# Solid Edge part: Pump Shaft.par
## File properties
Title: Pump Shaft
Author: Dan
Comments: Rely Investment Cast Shrinkage  2.6%:  X 1.026 Measured Sizes.  EN 19   Die No 3669  Machine  Heat treat to Condition T  Grind  Nitride, Silver Grey Finish
Template: Normal Colour.par
Last saved by: Dan
Revision: 112
Application: Solid Edge
Density: 7.85 kg/dm^3
Accuracy: 0.99
Document Number: P52-003
Project Name: Piston Pump P52
Material: steel en19
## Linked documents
SPLINE1 005UZCMR.par
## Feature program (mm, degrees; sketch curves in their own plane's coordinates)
sketch for "unnamed Protrusion 1" plane through (0, 0, 0) normal (0, 0, 1) x-axis (1, 0, 0)
extrude "unnamed Protrusion 1" add finite 92 along +normal
boolean "unnamed Boolean 1"
sketch for "ExtrudedCutout_1" plane through (0, 0, 0) normal (0, 0, -1) x-axis (0, 1, 0)
  line (15.7162, 3) -> (17.2409, 3)
  arc centre (0, 0) radius 17.5 from (17.2409, -3) to (17.2409, 3) ccw
  line (17.2409, -3) -> (15.7162, -3)
  arc centre (15.7162, -3.8) radius 0.8 from (15.7162, -3) to (15.3507, -4.5116) ccw
  arc centre (0, 0) radius 16 from (15.3507, -4.5116) to (14.0448, -7.6644) cw
  arc centre (13.8001, -8.426) radius 0.8 from (13.2344, -8.9917) to (14.0448, -7.6644) cw
  line (13.2344, -8.9917) -> (14.3125, -10.0699)
  arc centre (0, 0) radius 17.5 from (10.0699, -14.3125) to (14.3125, -10.0699) ccw
  line (10.0699, -14.3125) -> (8.9917, -13.2344)
  arc centre (8.426, -13.8001) radius 0.8 from (8.9917, -13.2344) to (7.6644, -14.0448) ccw
  arc centre (0, 0) radius 16 from (7.6644, -14.0448) to (4.5116, -15.3507) cw
  arc centre (3.8, -15.7162) radius 0.8 from (3, -15.7162) to (4.5116, -15.3507) cw
  line (3, -15.7162) -> (3, -17.2409)
  arc centre (0, 0) radius 17.5 from (-3, -17.2409) to (3, -17.2409) ccw
  line (-3, -17.2409) -> (-3, -15.7162)
  arc centre (-3.8, -15.7162) radius 0.8 from (-3, -15.7162) to (-4.5116, -15.3507) ccw
  arc centre (0, 0) radius 16 from (-4.5116, -15.3507) to (-7.6644, -14.0448) cw
  arc centre (-8.426, -13.8001) radius 0.8 from (-8.9917, -13.2344) to (-7.6644, -14.0448) cw
  line (-8.9917, -13.2344) -> (-10.0699, -14.3125)
  arc centre (0, 0) radius 17.5 from (-14.3125, -10.0699) to (-10.0699, -14.3125) ccw
  line (-14.3125, -10.0699) -> (-13.2344, -8.9917)
  arc centre (-13.8001, -8.426) radius 0.8 from (-13.2344, -8.9917) to (-14.0448, -7.6644) ccw
  arc centre (0, 0) radius 16 from (-14.0448, -7.6644) to (-15.3507, -4.5116) cw
  arc centre (-15.7162, -3.8) radius 0.8 from (-15.7162, -3) to (-15.3507, -4.5116) cw
  line (-15.7162, -3) -> (-17.2409, -3)
  arc centre (0, 0) radius 17.5 from (-17.2409, 3) to (-17.2409, -3) ccw
  line (-17.2409, 3) -> (-15.7162, 3)
  arc centre (-15.7162, 3.8) radius 0.8 from (-15.7162, 3) to (-15.3507, 4.5116) ccw
  arc centre (0, 0) radius 16 from (-15.3507, 4.5116) to (-14.0448, 7.6644) cw
  arc centre (-13.8001, 8.426) radius 0.8 from (-13.2344, 8.9917) to (-14.0448, 7.6644) cw
  line (-13.2344, 8.9917) -> (-14.3125, 10.0699)
  arc centre (0, 0) radius 17.5 from (-10.0699, 14.3125) to (-14.3125, 10.0699) ccw
  line (-10.0699, 14.3125) -> (-8.9917, 13.2344)
  arc centre (-8.426, 13.8001) radius 0.8 from (-8.9917, 13.2344) to (-7.6644, 14.0448) ccw
  arc centre (0, 0) radius 16 from (-7.6644, 14.0448) to (-4.5116, 15.3507) cw
  arc centre (-3.8, 15.7162) radius 0.8 from (-3, 15.7162) to (-4.5116, 15.3507) cw
  line (-3, 15.7162) -> (-3, 17.2409)
  arc centre (0, 0) radius 17.5 from (3, 17.2409) to (-3, 17.2409) ccw
  line (3, 17.2409) -> (3, 15.7162)
  arc centre (3.8, 15.7162) radius 0.8 from (3, 15.7162) to (4.5116, 15.3507) ccw
  arc centre (0, 0) radius 16 from (4.5116, 15.3507) to (7.6644, 14.0448) cw
  arc centre (8.426, 13.8001) radius 0.8 from (8.9917, 13.2344) to (7.6644, 14.0448) cw
  line (8.9917, 13.2344) -> (10.0699, 14.3125)
  arc centre (0, 0) radius 17.5 from (14.3125, 10.0699) to (10.0699, 14.3125) ccw
  line (14.3125, 10.0699) -> (13.2344, 8.9917)
  arc centre (13.8001, 8.426) radius 0.8 from (13.2344, 8.9917) to (14.0448, 7.6644) ccw
  arc centre (0, 0) radius 16 from (14.0448, 7.6644) to (15.3507, 4.5116) cw
  arc centre (15.7162, 3.8) radius 0.8 from (15.7162, 3) to (15.3507, 4.5116) cw
extrude "ExtrudedCutout_1" cut finite 40 along -normal
sketch for "unnamed Cutout 1" plane through (0, 0, 0) normal (0, 0, 1) x-axis (1, 0, 0)
extrude "unnamed Cutout 1" cut to key point along +normal
pattern "unnamed Pattern 1" of "unnamed Cutout 1"
extrude "unnamed Cutout 2" cut finite 40
extrude "unnamed Cutout 3" cut finite 40
extrude "unnamed Cutout 4" cut finite 40
extrude "unnamed Cutout 5" cut finite 40
extrude "unnamed Cutout 6" cut finite 40
extrude "unnamed Cutout 7" cut finite 40
extrude "unnamed Cutout 8" cut finite 40
sketch for "ExtrudedCutout_12" plane through (0, 0, 0) normal (0, 0, -1) x-axis (-1, 0, 0)
extrude "ExtrudedCutout_12" cut finite 40 along -normal
sketch for "unnamed RevolvedCutout 1" plane through (0, 0, 0) normal (0, -1, 0) x-axis (1, 0, 0)
  line (17.5, 40) -> (15, 40)
  line (15, 40) -> (15, 43)
  line (15, 43) -> (17.5, 43)
revolve "unnamed RevolvedCutout 1" cut full turn 360 deg
sketch for "unnamed RevolvedProtrusion 1" plane through (0, 0, 0) normal (1, 0, 0) x-axis (0, 1, 0)
  line (0, 92) -> (20, 92)
  line (20, 92) -> (20, 94)
  line (20, 94) -> (22, 94)
  line (22, 94) -> (22, 106)
  line (22, 106) -> (45, 106)
  line (45, 106) -> (45, 140)
  line (45, 140) -> (15.5086, 156.897)
  arc centre (17, 159.5) radius 3 from (14, 159.5) to (15.5086, 156.897) ccw
  line (14, 159.5) -> (14, 189.5)
  line (14, 189.5) -> (0, 189.5)
revolve "unnamed RevolvedProtrusion 1" add full turn 360 deg about sketch line (0, 189.5) -> (0, 92)
sketch for "unnamed RevolvedCutout 2" plane through (0, 0, 0) normal (1, 0, 0) x-axis (0, 1, 0)
  line (-44.2691, 105.6092) -> (-14.1455, 114.8189)
  line (-14.1455, 114.8189) -> (-25.8403, 153.0711)
  line (-25.8403, 153.0711) -> (-40.9152, 153.0711)
revolve "unnamed RevolvedCutout 2" cut full turn 360 deg about sketch line (2.0265, 137.1696) -> (-6.8733, 166.2795)
sketch for "Cutout_2" plane through (0, -0.5172, 106) normal (0, 0, -1) x-axis (-1, 0, 0)
  hole centre (0, 32.8172) bore radius 5
hole "Cutout_2" diameter 10 finite
sketch for "unnamed RevolvedCutout 3" plane through (0, 0, 0) normal (1, 0, 0) x-axis (0, 1, 0)
  line (41.5, 106) -> (41.5, 122.5158)
  arc centre (44.5, 122.5158) radius 3 from (44.5, 125.5158) to (41.5, 122.5158) ccw
  line (44.5, 125.5158) -> (49.5655, 125.5158)
  line (49.5655, 125.5158) -> (49.5655, 106)
  line (49.5655, 106) -> (41.5, 106)
revolve "unnamed RevolvedCutout 3" cut full turn 360 deg about sketch line (1.0045, 119.4508) -> (3.9475, 109.8248)
sketch for "unnamed RevolvedCutout 4" plane through (0, 0, 0) normal (1, 0, 0) x-axis (0, 1, 0)
revolve "unnamed RevolvedCutout 4" cut full turn 360 deg about sketch line (6.1623, 123.6419) -> (-1.2967, 148.0393)
sketch for "unnamed Cutout 9" plane through (0, 0, 0) normal (1, 0, 0) x-axis (0, 1, 0)
extrude "unnamed Cutout 9" cut through
lofted protrusion "unnamed LoftedProtrusion 1"
sketch for "Hole_9" plane through (0, 0, 189.5) normal (0, 0, 1) x-axis (0, 1, 0)
hole "Hole_9" diameter 4 finite  CounterSinkAngle = 60 deg; VBottomAngle = 118 deg
sketch for "Hole_10" plane through (0, 0, 0) normal (0, 0, -1) x-axis (0, 1, 0)
hole "Hole_10" diameter 4 finite  CounterSinkAngle = 60 deg; VBottomAngle = 118 deg
sketch for "unnamed RevolvedCutout 5" plane through (0, 0, 0) normal (0, -1, 0) x-axis (1, 0, 0)
revolve "unnamed RevolvedCutout 5" cut full turn 360 deg
sketch for "Hole_11" plane through (0, 0, 0) normal (-0.382683, -0.92388, 0) x-axis (0, 0, -1)
  hole centre (-18.5, 0) bore radius 4.15
  line (21.0233, 148.5704) -> (25.1148, 135.1876)
hole "Hole_11" diameter 8.3 through  VBottomAngle = 118 deg
sketch for "unnamed RevolvedCutout 6" plane through (0, 0, 0) normal (1, 0, 0) x-axis (0, 1, 0)
revolve "unnamed RevolvedCutout 6" cut full turn 360 deg
fillet "Round_1" radius 0.6
chamfer "Chamfer_1" setback 1.5
sketch for "unnamed RevolvedCutout 7" plane through (0, 0, 0) normal (1, 0, 0) x-axis (0, 1, 0)
  line (19.1444, 3.6444) -> (15.5, 0)
revolve "unnamed RevolvedCutout 7" cut finite 360 deg
base feature "unnamed BaseFeature 1"
delete holes assoc c "unnamed DeleteHolesAssocC 1"
Other named dimensions: "CopyConstruction_2": XScale = 1; YScale = 1; ZScale = 1
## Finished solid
Body 1: solid body, 67 faces, 194 edges, 128 vertices.
  Faces by surface: plane 34, cylinder 33
  Edges by curve: line 128, circle 66
Body 2: solid body, 149 faces, 377 edges, 230 vertices.
  Faces by surface: cylinder 71, plane 50, cone 23, torus 4, spline 1
  Edges by curve: circle 149, line 138, intersection 79, ellipse 10, curve on surface 1
Bounding box of the edges (mm; curved faces can reach further): 90.000 x 84.576 x 189.500, from (-45, -39.5763, 0) to (45.0001, 45, 189.5).
Cylindrical faces by radius (mm): R0.6 x1, R0.8 x36, R2 x2, R4.15 x1, R5 x1, R14 x1, R15 x1, R15.9 x10, R16 x8, R16.4 x1, R16.7 x8, R17.4 x16, R17.5 x2, R18 x8, R18.18 x1, R20 x1, R20.5 x1, R21.5 x2, R22 x2, R45 x1
Conical faces (half-angle, radius in mm at the cone's reference point): 17 deg R34.7934 x1, 30 deg R4 x2, 45 deg R12.5 x1, 45 deg R19.1444 x16, 59 deg R2 x2, 73 deg R43.3682 x1
Toroidal faces (ring radius, tube radius in mm): R17 r3 x1, R42.491 r3 x1, R44.4 r0.6 x2
Planar faces by outward normal: +x 7, +y 6, +z 12, -x 7, -y 6, -z 16, oblique 30
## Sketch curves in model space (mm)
line (0, 15.5086, 156.897) -> (0, 19.2384, 154.4084)
line (0, -15.5086, 156.897) -> (0, -21.8827, 141.8364)
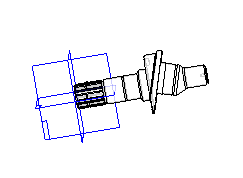
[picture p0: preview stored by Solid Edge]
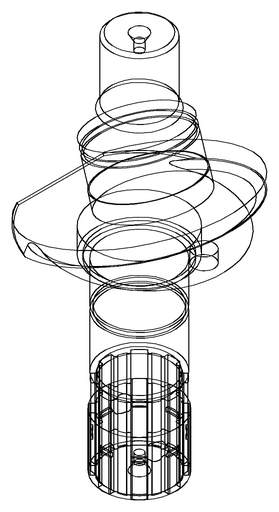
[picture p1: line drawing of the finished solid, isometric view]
